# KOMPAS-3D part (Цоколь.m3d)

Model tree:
1. Эскиз:1
2. Операция выдавливания:1
     Расстояние 1 = 20
3. Эскиз:2
4. Операция выдавливания:2
     Расстояние 1 = 1.5; Угол 1 = 45
5. Эскиз:5
6. Спираль цилиндрическая:2
     Число витков = 4; Шаг = 3.75; Высота = 15; Диаметр 1 = 27; Диаметр 2 = 10
7. Эскиз:6
8. Вырезать кинематический элемент:2
9. Вырезать элемент выдавливания:3
     Расстояние 1 = 19
10. Вырезать элемент выдавливания:4
     Расстояние 1 = 19
11. Эскиз:7
12. Операция выдавливания:3
     Расстояние 1 = 4; Угол 1 = 45
13. Эскиз:8
14. Операция вращения:1
     Угол 1 = 360
15. Скругление:1
     Радиус = 0.1
16. Эскиз:9
17. Вырезать элемент выдавливания:5
     Расстояние 1 = 19
